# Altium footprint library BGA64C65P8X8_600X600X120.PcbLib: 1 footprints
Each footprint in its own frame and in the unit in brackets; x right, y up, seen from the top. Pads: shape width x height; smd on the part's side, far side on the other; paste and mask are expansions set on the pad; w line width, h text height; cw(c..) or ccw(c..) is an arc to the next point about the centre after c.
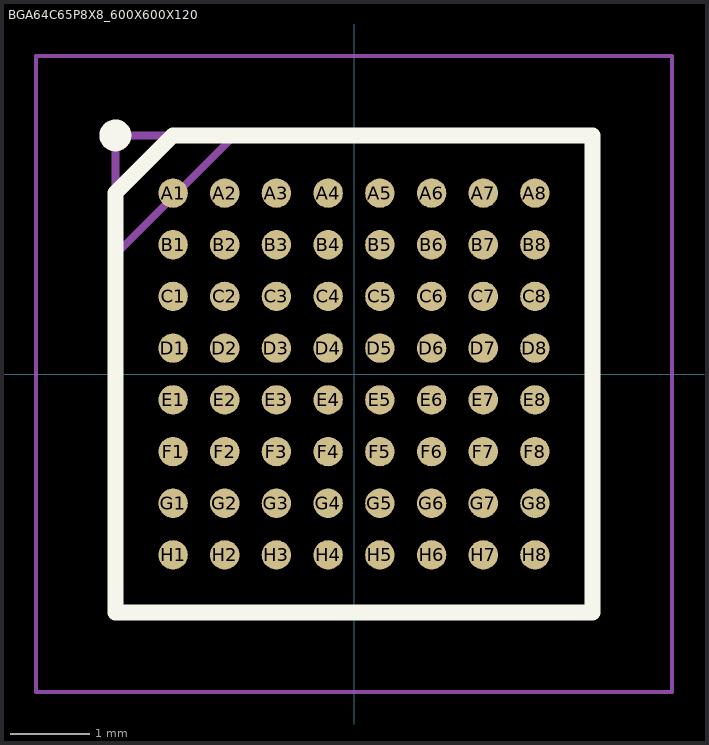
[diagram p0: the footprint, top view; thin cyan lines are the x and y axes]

## BGA64C65P8X8_600X600X120 [mm]
pads (64):
  round 0.37 smd: A1(-2.275,2.275) A2(-1.625,2.275) A3(-0.975,2.275) A4(-0.325,2.275) A5(0.325,2.275) A6(0.975,2.275) A7(1.625,2.275) A8(2.275,2.275) B1(-2.275,1.625) B2(-1.625,1.625) B3(-0.975,1.625) B4(-0.325,1.625) B5(0.325,1.625) B6(0.975,1.625) B7(1.625,1.625) B8(2.275,1.625) C1(-2.275,0.975) C2(-1.625,0.975) C3(-0.975,0.975) C4(-0.325,0.975) C5(0.325,0.975) C6(0.975,0.975) C7(1.625,0.975) C8(2.275,0.975) D1(-2.275,0.325) D2(-1.625,0.325) D3(-0.975,0.325) D4(-0.325,0.325) D5(0.325,0.325) D6(0.975,0.325) D7(1.625,0.325) D8(2.275,0.325) E1(-2.275,-0.325) E2(-1.625,-0.325) E3(-0.975,-0.325) E4(-0.325,-0.325) E5(0.325,-0.325) E6(0.975,-0.325) E7(1.625,-0.325) E8(2.275,-0.325) F1(-2.275,-0.975) F2(-1.625,-0.975) F3(-0.975,-0.975) F4(-0.325,-0.975) F5(0.325,-0.975) F6(0.975,-0.975) F7(1.625,-0.975) F8(2.275,-0.975) G1(-2.275,-1.625) G2(-1.625,-1.625) G3(-0.975,-1.625) G4(-0.325,-1.625) G5(0.325,-1.625) G6(0.975,-1.625) G7(1.625,-1.625) G8(2.275,-1.625) H1(-2.275,-2.275) H2(-1.625,-2.275) H3(-0.975,-2.275) H4(-0.325,-2.275) H5(0.325,-2.275) H6(0.975,-2.275) H7(1.625,-2.275) H8(2.275,-2.275)
Top Overlay:
  circle w0.2: c-3,3 r0.1
  lines w0.2: -3,-3 3,-3 3,3 -2.275,3 -3,2.275 -3,-3
Mechanical 15:
  lines w0.1: -3,1.5 -1.5,3 ; -3,-3 3,-3 3,3 -3,3 -3,-3
Mechanical 20:
  lines w0.05: -4,-4 4,-4 4,4 -4,4 -4,-4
